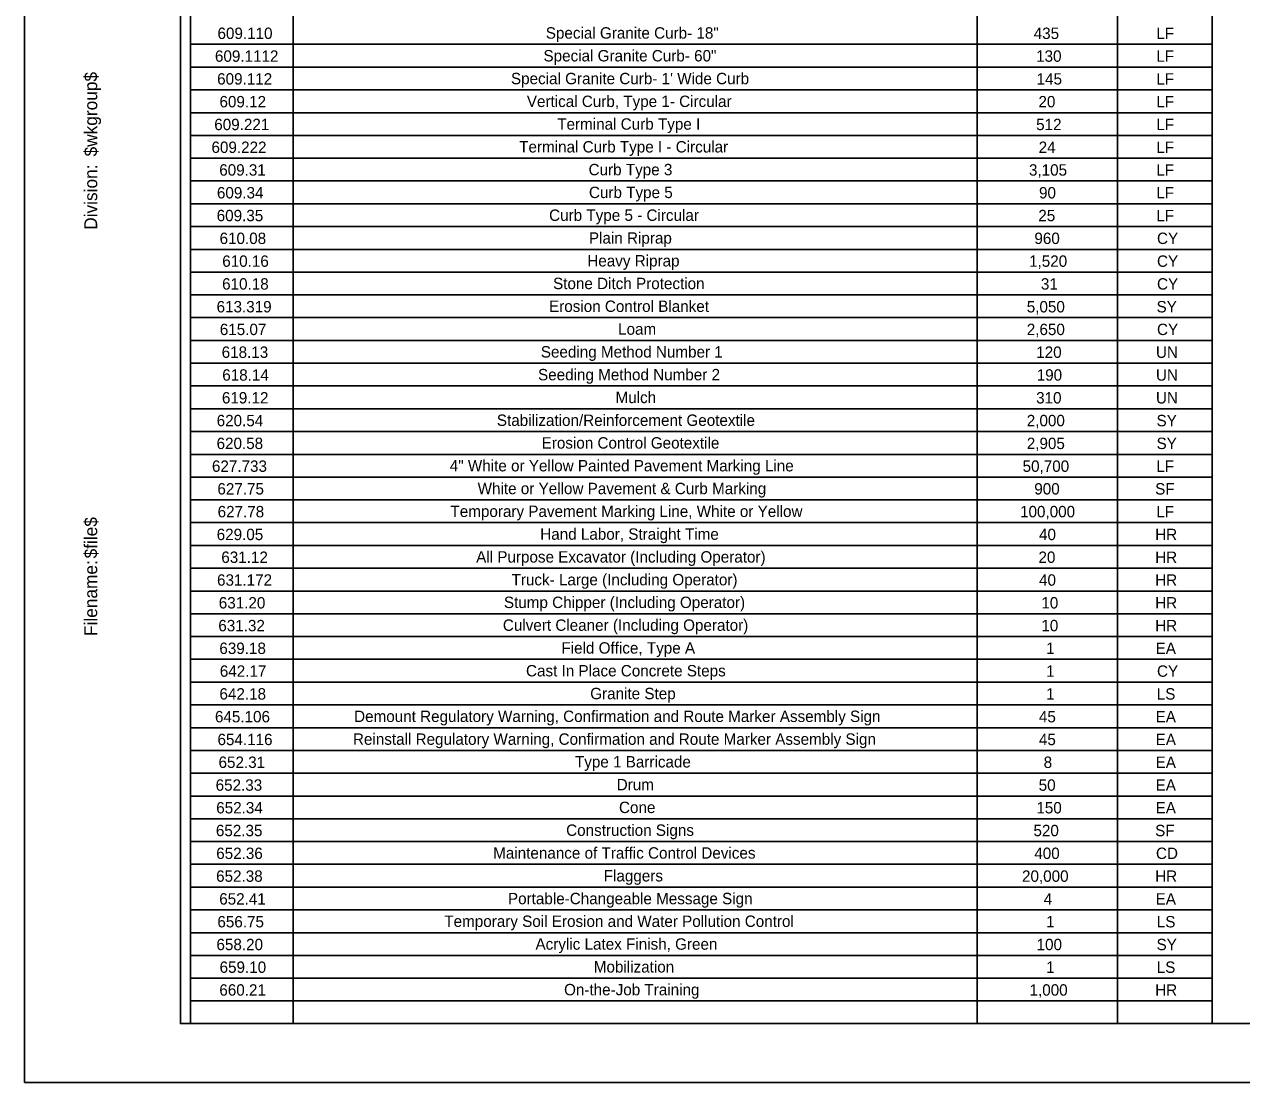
# Model space of a CAD drawing. Extents: x -0.13 to 2.7, y -0.05 to 1.78.
# Drawn here: x -0.135 to 0.917, y -0.051 to 0.864 of the extents above; entities that cross this region are included whole.
import ezdxf

# ---------------------------------------------------------------- set-up
doc = ezdxf.new("R2010")
doc.units = 0
for name, color, linetype in [('ANNOTATION', 7, 'Continuous'), ('BORDER', 7, 'Continuous'), ('PLOT BOUNDARY', 7, 'Continuous')]:
    doc.layers.add(name, color=color, linetype=linetype)

msp = doc.modelspace()

# ---------------------------------------------------------------- linework, layer by layer
at = {"layer": 'BORDER'}
for p, q in [((0.0974, 1.7323), (0.0974, -0.0001)), ((0.6887, 1.7323), (0.6887, -0.0001)), ((0.8101, 1.7323), (0.8101, -0.0001)), ((0.0088, 0.8464), (0.8921, 0.8464)), ((0.0088, 0.8267), (0.8921, 0.8267)), ((0.0088, 0.807), (0.8921, 0.807)), ((0.0088, 0.7873), (0.8921, 0.7873)), ((0.0088, 0.7676), (0.8921, 0.7676)), ((0.0088, 0.748), (0.8921, 0.748)), ((0.0088, 0.7283), (0.8921, 0.7283)), ((0.0088, 0.7086), (0.8921, 0.7086)), ((0.0088, 0.6889), (0.8921, 0.6889)), ((0.0088, 0.6692), (0.8921, 0.6692)), ((0.0088, 0.6495), (0.8921, 0.6495)), ((0.0088, 0.6298), (0.8921, 0.6298)), ((0.0088, 0.6102), (0.8921, 0.6102)), ((0.0088, 0.5905), (0.8921, 0.5905)), ((0.0088, 0.5708), (0.8921, 0.5708)), ((0.0088, 0.5511), (0.8921, 0.5511)), ((0.0088, 0.5314), (0.8921, 0.5314)), ((0.0088, 0.5117), (0.8921, 0.5117)), ((0.0088, 0.492), (0.8921, 0.492)), ((0.0088, 0.4723), (0.8921, 0.4723)), ((0.0088, 0.4527), (0.8921, 0.4527)), ((0.0088, 0.433), (0.8921, 0.433)), ((0.0088, 0.4133), (0.8921, 0.4133)), ((0.0088, 0.3936), (0.8921, 0.3936)), ((0.0088, 0.3739), (0.8921, 0.3739)), ((0.0088, 0.3542), (0.8921, 0.3542)), ((0.0088, 0.3345), (0.8921, 0.3345)), ((0.0088, 0.3149), (0.8921, 0.3149)), ((0.0088, 0.2952), (0.8921, 0.2952)), ((0.0088, 0.2755), (0.8921, 0.2755)), ((0.0088, 0.2558), (0.8921, 0.2558)), ((0.0088, 0.2361), (0.8921, 0.2361)), ((0.0088, 0.2164), (0.8921, 0.2164)), ((0.0088, 0.1967), (0.8921, 0.1967)), ((0.0088, 0.1771), (0.8921, 0.1771)), ((0.0088, 0.1574), (0.8921, 0.1574)), ((0.0088, 0.1377), (0.8921, 0.1377)), ((0.0088, 0.118), (0.8921, 0.118)), ((0.0088, 0.0983), (0.8921, 0.0983)), ((0.0088, 0.0786), (0.8921, 0.0786)), ((0.0088, 0.0589), (0.8921, 0.0589)), ((0.0088, 0.0393), (0.8921, 0.0393)), ((0.0088, 0.0196), (0.8921, 0.0196))]:
    msp.add_line(p, q, dxfattribs=at)
msp.add_lwpolyline([(0, 1.75), (2.6667, 1.75), (2.6667, 0), (0, 0)], close=True, dxfattribs=at)
for points in [[(0.0088, 0), (0.0088, 1.75)], [(0.8921, 1.75), (0.8921, 0)]]:
    msp.add_lwpolyline(points, dxfattribs=at)
at = {"layer": 'PLOT BOUNDARY'}
msp.add_lwpolyline([(-0.1349, -0.051), (2.6984, -0.051), (2.6984, 1.7823), (-0.1349, 1.7823)], close=True, dxfattribs=at)

# ---------------------------------------------------------------- texts
at = {"layer": 'ANNOTATION'}
for s, height, p in [('609.110', 0.00984, (0.0321, 0.851)), ('Special Granite Curb- 18"', 0.009843, (0.3159, 0.8513)), ('435', 0.00984, (0.7377, 0.851)), ('LF', 0.00984, (0.8437, 0.851)), ('Special Granite Curb- 60"', 0.009843, (0.3139, 0.8316)), ('609.1112', 0.00984, (0.0299, 0.8313)), ('130', 0.00984, (0.7398, 0.8313)), ('LF', 0.00984, (0.8437, 0.8313)), ('609.112', 0.00984, (0.0318, 0.8116)), ("Special Granite Curb- 1' Wide Curb", 0.009843, (0.2858, 0.8119)), ('145', 0.00984, (0.7402, 0.8116)), ('LF', 0.00984, (0.8437, 0.8116)), ('609.12', 0.00984, (0.0338, 0.7919)), ('Vertical Curb, Type 1- Circular', 0.009843, (0.2995, 0.7922)), ('20', 0.00984, (0.7418, 0.7919)), ('LF', 0.00984, (0.8437, 0.7919)), ('609.221', 0.00984, (0.0293, 0.7722)), ('Terminal Curb Type I', 0.009843, (0.3258, 0.7726)), ('512', 0.00984, (0.7398, 0.7722)), ('LF', 0.00984, (0.8437, 0.7722)), ('609.222', 0.00984, (0.0269, 0.7525)), ('Terminal Curb Type I - Circular', 0.009843, (0.2929, 0.7529)), ('24', 0.00984, (0.742, 0.7525)), ('LF', 0.00984, (0.8437, 0.7525)), ('609.31', 0.00984, (0.0336, 0.7329)), ('Curb Type 3', 0.009843, (0.3529, 0.7332)), ('3,105', 0.00984, (0.7336, 0.7329)), ('LF', 0.00984, (0.8437, 0.7329)), ('609.34', 0.00984, (0.0316, 0.7132)), ('Curb Type 5', 0.009843, (0.3532, 0.7135)), ('90', 0.00984, (0.7423, 0.7132)), ('LF', 0.00984, (0.8437, 0.7132)), ('609.35', 0.00984, (0.0314, 0.6935)), ('Curb Type 5 - Circular', 0.009843, (0.3188, 0.6938)), ('25', 0.00984, (0.7417, 0.6935)), ('LF', 0.00984, (0.8437, 0.6935)), ('Plain Riprap', 0.009843, (0.3532, 0.6741)), ('610.08', 0.00984, (0.0339, 0.6738)), ('960', 0.00984, (0.7383, 0.6738)), ('CY', 0.00984, (0.8443, 0.6738)), ('610.16', 0.00984, (0.0362, 0.6541)), ('Heavy Riprap', 0.009843, (0.3518, 0.6544)), ('1,520', 0.00984, (0.7337, 0.6541)), ('CY', 0.00984, (0.8443, 0.6541)), ('610.18', 0.00984, (0.0361, 0.6344)), ('Stone Ditch Protection', 0.009843, (0.3222, 0.6348)), ('31', 0.00984, (0.7439, 0.6344)), ('CY', 0.00984, (0.8443, 0.6344)), ('613.319', 0.00984, (0.0313, 0.6147)), ('Erosion Control Blanket', 0.009843, (0.3187, 0.6151)), ('5,050', 0.00984, (0.7317, 0.6147)), ('SY', 0.00984, (0.8439, 0.6147)), ('615.07', 0.00984, (0.0341, 0.5951)), ('Loam', 0.00984, (0.3784, 0.5954)), ('2,650', 0.00984, (0.7317, 0.5951)), ('CY', 0.00984, (0.8443, 0.5951)), ('618.13', 0.00984, (0.0357, 0.5754)), ('Seeding Method Number 1', 0.009843, (0.3116, 0.5757)), ('120', 0.00984, (0.7399, 0.5754)), ('UN', 0.00984, (0.8434, 0.5754)), ('618.14', 0.00984, (0.0362, 0.5557)), ('Seeding Method Number 2', 0.009843, (0.3092, 0.556)), ('190', 0.00984, (0.7403, 0.5557)), ('UN', 0.00984, (0.8434, 0.5557)), ('619.12', 0.00984, (0.0359, 0.536)), ('Mulch', 0.00984, (0.3762, 0.5363)), ('310', 0.00984, (0.7398, 0.536)), ('UN', 0.00984, (0.8434, 0.536)), ('620.54', 0.00984, (0.0314, 0.5163)), ('Stabilization/Reinforcement Geotextile', 0.009843, (0.2736, 0.5166)), ('2,000', 0.00984, (0.7317, 0.5163)), ('SY', 0.00984, (0.8439, 0.5163)), ('620.58', 0.00984, (0.0313, 0.4966)), ('Erosion Control Geotextile', 0.009843, (0.3123, 0.497)), ('2,905', 0.00984, (0.7317, 0.4966)), ('SY', 0.00984, (0.8439, 0.4966)), ('627.733', 0.00984, (0.0273, 0.4769)), ('4" White or Yellow Painted Pavement Marking Line', 0.009843, (0.2329, 0.4773)), ('50,700', 0.00984, (0.7281, 0.4769)), ('LF', 0.00984, (0.8437, 0.4769)), ('627.75', 0.00984, (0.032, 0.4573)), ('White or Yellow Pavement & Curb Marking', 0.009843, (0.257, 0.4576)), ('900', 0.00984, (0.7382, 0.4573)), ('SF', 0.00984, (0.8427, 0.4573)), ('627.78', 0.00984, (0.0322, 0.4376)), ('Temporary Pavement Marking Line, White or Yellow', 0.009843, (0.2335, 0.4379)), ('100,000', 0.00984, (0.7259, 0.4376)), ('LF', 0.00984, (0.8437, 0.4376)), ('629.05', 0.00984, (0.0314, 0.4179)), ('Hand Labor, Straight Time', 0.009843, (0.3111, 0.4182)), ('40', 0.00984, (0.7423, 0.4179)), ('HR', 0.00984, (0.8427, 0.4179)), ('631.12', 0.00984, (0.0354, 0.3982)), ('All Purpose Excavator (Including Operator)', 0.009843, (0.2557, 0.3985)), ('20', 0.00984, (0.7418, 0.3982)), ('HR', 0.00984, (0.8427, 0.3982)), ('631.172', 0.00984, (0.0317, 0.3785)), ('Truck- Large (Including Operator)', 0.009843, (0.2863, 0.3788)), ('40', 0.00984, (0.7423, 0.3785)), ('HR', 0.00984, (0.8427, 0.3785)), ('631.20', 0.00984, (0.0332, 0.3588)), ('Stump Chipper (Including Operator)', 0.009843, (0.2797, 0.3592)), ('10', 0.00984, (0.7443, 0.3588)), ('HR', 0.00984, (0.8427, 0.3588)), ('631.32', 0.00984, (0.0328, 0.3391)), ('Culvert Cleaner (Including Operator)', 0.009843, (0.2788, 0.3395)), ('10', 0.00984, (0.7443, 0.3391)), ('HR', 0.00984, (0.8427, 0.3391)), ('639.18', 0.00984, (0.0337, 0.3195)), ('Field Office, Type A', 0.009843, (0.3294, 0.3198)), ('1', 0.00984, (0.7484, 0.3195)), ('EA', 0.00984, (0.8431, 0.3195)), ('642.17', 0.00984, (0.0341, 0.2998)), ('Cast In Place Concrete Steps', 0.009843, (0.2988, 0.3001)), ('1', 0.00984, (0.7484, 0.2998)), ('CY', 0.00984, (0.8443, 0.2998)), ('642.18', 0.00984, (0.0338, 0.2801)), ('Granite Step', 0.009843, (0.3543, 0.2804)), ('1', 0.00984, (0.7484, 0.2801)), ('LS', 0.00984, (0.8441, 0.2801)), ('645.106', 0.00984, (0.0299, 0.2604)), ('Demount Regulatory Warning, Confirmation and Route Marker Assembly Sign  ', 0.009843, (0.1502, 0.2607)), ('45', 0.00984, (0.7422, 0.2604)), ('EA', 0.00984, (0.8431, 0.2604)), ('654.116', 0.00984, (0.0321, 0.2407)), ('Reinstall Regulatory Warning, Confirmation and Route Marker Assembly Sign ', 0.009843, (0.1492, 0.241)), ('45', 0.00984, (0.7422, 0.2407)), ('EA', 0.00984, (0.8431, 0.2407)), ('Type 1 Barricade', 0.009843, (0.3411, 0.2214)), ('652.31', 0.00984, (0.033, 0.221)), ('8', 0.00984, (0.7463, 0.221)), ('EA', 0.00984, (0.8431, 0.221)), ('652.33', 0.00984, (0.0305, 0.2013)), ('Drum', 0.00984, (0.3772, 0.2017)), ('50', 0.00984, (0.742, 0.2013)), ('EA', 0.00984, (0.8431, 0.2013)), ('652.34', 0.00984, (0.031, 0.1817)), ('Cone', 0.00984, (0.3792, 0.182)), ('150', 0.00984, (0.74, 0.1817)), ('EA', 0.00984, (0.8431, 0.1817)), ('652.35', 0.00984, (0.0307, 0.162)), ('Construction Signs', 0.009843, (0.3335, 0.1623)), ('520', 0.00984, (0.7375, 0.162)), ('SF', 0.00984, (0.8427, 0.162)), ('652.36', 0.00984, (0.031, 0.1423)), ('Maintenance of Traffic Control Devices', 0.009843, (0.2704, 0.1426)), ('400', 0.00984, (0.7382, 0.1423)), ('CD', 0.00984, (0.8434, 0.1423)), ('652.38', 0.00984, (0.0309, 0.1226)), ('Flaggers', 0.00984, (0.366, 0.1229)), ('20,000', 0.00984, (0.7276, 0.1226)), ('HR', 0.00984, (0.8427, 0.1226)), ('652.41', 0.00984, (0.0336, 0.1029)), ('Portable-Changeable Message Sign', 0.009843, (0.2832, 0.1032)), ('4', 0.00984, (0.7464, 0.1029)), ('EA', 0.00984, (0.8431, 0.1029)), ('656.75', 0.00984, (0.032, 0.0832)), ('Temporary Soil Erosion and Water Pollution Control ', 0.009843, (0.2282, 0.0836)), ('1', 0.00984, (0.7484, 0.0832)), ('LS', 0.00984, (0.8441, 0.0832)), ('Acrylic Latex Finish, Green', 0.009843, (0.307, 0.0639)), ('658.20', 0.00984, (0.0312, 0.0635)), ('100', 0.00984, (0.7402, 0.0635)), ('SY', 0.00984, (0.8439, 0.0635)), ('659.10', 0.00984, (0.0339, 0.0439)), ('Mobilization', 0.009843, (0.3574, 0.0442)), ('1', 0.00984, (0.7484, 0.0439)), ('LS', 0.00984, (0.8441, 0.0439)), ('660.21', 0.00984, (0.0337, 0.0242)), ('On-the-Job Training', 0.009843, (0.3317, 0.0245)), ('1,000', 0.00984, (0.7341, 0.0242)), ('HR', 0.00984, (0.8427, 0.0242))]:
    msp.add_text(s, height=height, dxfattribs=at).set_placement(p)
at = {"layer": 'BORDER'}
for s, p in [('$wkgroup$', (-0.0719, 0.7495)), ('Division:', (-0.0719, 0.6861)), ('$file$', (-0.0719, 0.4021)), ('Filename:', (-0.0719, 0.335))]:
    msp.add_text(s, height=0.01116, rotation=90, dxfattribs=at).set_placement(p)

doc.saveas('drawing.dxf')
